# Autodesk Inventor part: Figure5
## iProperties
Created: 2001-12
Part Number: Figure5
Document SubType Name: Modeling
Designer: CADSoft
Control State: 0
Master: False
Checked Out: False
Shininess: 77.0
Angle Display Precision: 2
Document Length Units: 11269
Document Angle Units: 11279
Document Time Units: 11290
Document Mass Units: 11283
Document Length Units Precision: 3
Document Angle Units Precision: 2
Density: 0.0
Volumn: 0.0
Area: 0.0
PropertySet Name: Model Information
Author: CADSoft
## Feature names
1. Loft1
